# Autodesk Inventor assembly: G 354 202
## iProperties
Company: Mayer & Müller AG Schaltgeräte
Created: 2005-10
Part Number: G 354 202
Document SubType Name: Assembly
Designer: I.Baliuc
Manufacturer: Standard
Standards Organization: Custom
Description: Schalthebel, kompl.
Mass: 914.746 g
Surface Area: 405.806 cm^2
Volume: 116.349 cm^3
Density: 7.86205 g/cm^3
Author: T.Messerschmitt
Revision Number: 354202
Comments: Beachten die Bauanlage d. Buchse!
